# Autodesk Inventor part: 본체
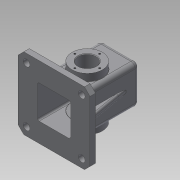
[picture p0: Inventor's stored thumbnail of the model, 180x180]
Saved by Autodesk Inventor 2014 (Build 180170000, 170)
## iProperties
Created: 2016-02
Part Number: 본체
Material: Generic
Document SubType Name: Modeling
Designer: user
Density: 1 g/cm^3
Appearance: Default
Author: user
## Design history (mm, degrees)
sketch "Sketch1"
  geometry: L1 (-35, -60)-(35, -60); L2 (35, -60)-(35, 60); L3 (35, 60)-(-35, 60); L4 (-35, 60)-(-35, -60); L5 (-35, -60)-(35, 60); L6 (35, -60)-(-35, 60); 1 further point
  constraints: 12 end point, 2 midpoint
extrude "Extrusion1" new body sketch "Sketch1" stored distance "d6" = 70; taper "d7" = 0 deg
sketch "Sketch3"
  geometry: L1 (70, -70)-(70, 0) reference; L2 (0, 0)-(70, 0) reference; L3 (0, 0)-(0, -70) reference; L4 (70, -70)-(0, -70) reference; L5 (-30, -100)-(100, -100); L6 (100, -100)-(100, 30); L7 (100, 30)-(-30, 30); L8 (-30, 30)-(-30, -100); L9 (-30, -100)-(100, 30); L10 (100, -100)-(-30, 30); 1 further point
  constraints: 12 end point, 2 midpoint
extrude "Extrusion2" join sketch "Sketch3" distance "d9" = 10; taper "d10" = 0 deg
sketch "Sketch4"
  geometry: C1 r 27.5 at (0, 0); 1 further point
  constraints: 1 centre point, 1 coincident
extrude "Extrusion3" join sketch "Sketch4" distance "d11" = 13; taper "d12" = 0 deg
mirror "Mirror1"
sketch "Sketch5"
  geometry: L1 (-65, -60)-(-65, -50) reference; L2 (-65, -50)-(-35, -50) reference; L3 (-35, -50)-(-35, 60) reference; L4 (-35, 60)-(35, 60) reference; L5 (35, 60)-(35, -50) reference; L6 (35, -50)-(65, -50) reference; L7 (65, -50)-(65, -60) reference; L8 (65, -60)-(-65, -60) reference; L9 (20, 60)-(18.237, 70); L10 (18.237, 70)-(0, 70); L11 (0, 70)-(0, 60); L12 (0, 60)-(20, 60); 1 further point
  constraints: 8 end point, 1 horizontal, 1 midpoint, 1 point on line, 1 vertical
  dimensions: "d13" = 20 distance of L11.end L9.start; "d14" = 100 deg angle of L4 L9; "d15" = 10 distance of L10.end L11.end
revolve "Revolution1" sketch "Sketch5" stored, may be unused: angle "d16" = 90 deg
sketch "Sketch6"
  geometry: L1 (-65, -60)-(-65, -50) reference; L2 (-65, -50)-(-35, -50) reference; L3 (-35, -50)-(-35, 60) reference; L4 (-35, 60)-(-20, 60) reference; L5 (-20, 60)-(-18.237, 70) reference; L6 (-18.237, 70)-(18.237, 70) reference; L7 (18.237, 70)-(20, 60) reference; L8 (20, 60)-(35, 60) reference; L9 (35, 60)-(35, -50) reference; L10 (35, -50)-(65, -50) reference; L11 (65, -50)-(65, -60) reference; L12 (65, -60)-(-65, -60) reference; L13 (-50, -50)-(-35, 35.069); 1 further point
  constraints: 2 end point, 1 midpoint, 1 point on line
  dimensions: "d17" = 100 deg angle of L2 L13; "d18" = 15 distance from line of L1 L13.start
feature "Rib1" sketch "Sketch6" dims "d19" = 1, "d20" = 10, "d21" = 0, "d22" = 0, "d23" = 1, "d24" = 1
mirror "Mirror2"
sketch "Sketch8"
  geometry: L1 (27.5, 48)-(27.5, 35) reference; L2 (27.5, 35)-(60, 35) reference; L3 (60, 35)-(60, 20) reference; L4 (60, 20)-(70, 18.237) reference; L5 (70, 18.237)-(70, -18.237) reference; L6 (70, -18.237)-(60, -20) reference; L7 (60, -20)-(60, -35) reference; L8 (60, -35)-(27.5, -35) reference; L9 (27.5, -35)-(27.5, -48) reference; L10 (27.5, -48)-(-27.5, -48) reference; L11 (-27.5, -48)-(-27.5, -35) reference; L12 (-27.5, -35)-(-50, -35) reference; L13 (-50, -35)-(-50, -65) reference; L14 (-50, -65)-(-60, -65) reference; L15 (-60, -65)-(-60, 65) reference; L16 (-60, 65)-(-50, 65) reference; L17 (-50, 65)-(-50, 35) reference; L18 (-50, 35)-(-27.5, 35) reference; L19 (-27.5, 35)-(-27.5, 48) reference; L20 (-27.5, 48)-(27.5, 48) reference; L21 (-60, 30)-(55, 30); L22 (55, 30)-(55, -30); L23 (55, -30)-(-60, -30); L24 (-60, 30)-(-60, -30); 1 further point
  constraints: 8 end point, 2 point on line
  dimensions: "d25" = 5 distance between parallel lines of L18 L21; "d26" = 5 distance between parallel lines of L23 L12; "d27" = 5 distance between parallel lines of L7 L22
extrude "Extrusion4" cut sketch "Sketch8" stored distance "d28" = 60; taper "d29" = 0 deg
sketch "Sketch9"
  geometry: L1 (27.5, 48)-(27.5, 35) reference; L2 (27.5, 35)-(60, 35) reference; L3 (60, 35)-(60, 20) reference; L4 (60, 20)-(70, 18.237) reference; L5 (70, 18.237)-(70, -18.237) reference; L6 (70, -18.237)-(60, -20) reference; L7 (60, -20)-(60, -35) reference; L8 (60, -35)-(27.5, -35) reference; L9 (27.5, -35)-(27.5, -48) reference; L10 (27.5, -48)-(-27.5, -48) reference; L11 (-27.5, -48)-(-27.5, -35) reference; L12 (-27.5, -35)-(-50, -35) reference; L13 (-50, -35)-(-50, -65) reference; L14 (-50, -65)-(-60, -65) reference; L15 (-60, -65)-(-60, -30) reference; L16 (-60, -30)-(55, -30) reference; L17 (55, -30)-(55, 30) reference; L18 (55, 30)-(-60, 30) reference; L19 (-60, 30)-(-60, 65) reference; L20 (-60, 65)-(-50, 65) reference; L21 (-50, 65)-(-50, 35) reference; L22 (-50, 35)-(-27.5, 35) reference; L23 (-27.5, 35)-(-27.5, 48) reference; L24 (-27.5, 48)-(27.5, 48) reference; L25 (27.5, 30)-(0, 30); L26 (0, 30)-(0, 23); L27 (27.5, 30)-(20.5, 23); L28 (0, 23)-(20.5, 23); 1 further point
  constraints: 8 end point, 2 point on line
revolve "Revolution2" sketch "Sketch9" stored, may be unused: angle "d33" = 90 deg
mirror "Mirror3"
fillet "Fillet1" dims "d34" = 8
fillet "Fillet2" dims "d35" = 3
chamfer "Chamfer1" distance "d36" = 10; stored, may be unused: second distance "d37" = 2, angle "d38" = 45 deg
sketch "Sketch10"
  geometry: L1 (90, 100)-(-20, 100) reference; L2 (-30, 90)-(-30, -20) reference; C1 r 6 at (-15, 85); 1 further point
  constraints: 1 centre point
  dimensions: "d39" = 12 diameter of C1; "d40" = 15 distance from line of C1.centre L1; "d41" = 15 distance from line of C1.centre L2
extrude "Extrusion5" cut sketch "Sketch10" stored distance "d42" = 60; taper "d43" = 0 deg
mirror "Mirror4"
pattern_linear "Rectangular Pattern1"
fillet "Fillet3" dims "d47" = 8
fillet "Fillet4" dims "d48" = 0.5
sketch "Sketch11"
  geometry: L1 (-20.762, 45.72)-(20.762, 45.72); L2 (20.762, 45.72)-(20.762, 34.28); L3 (20.762, 34.28)-(-20.762, 34.28); L4 (-20.762, 34.28)-(-20.762, 45.72); L5 (-20.762, 45.72)-(20.762, 34.28); L6 (20.762, 45.72)-(-20.762, 34.28); L7 (-18.237, 70)-(18.237, 70) reference; L8 (35, -50)-(35, 52) reference; 1 further point
  constraints: 4 end point, 1 midpoint, 2 other
  dimensions: "d49" = 30 distance from line of point (0, 40) L7; "d50" = 35 distance from line of L8 point (0, 40)
emboss "Emboss1" sketch "Sketch11" dims "d51" = 0.5, "d52" = 0
fillet "Fillet5" dims "d53" = 3
fillet "Fillet6" dims "d54" = 3
fillet "Fillet7" dims "d55" = 3
hole "Hole1" diameter "d58" = 28; stored, may be unused: countersink angle "d62" = 90 deg, drill point angle "d64" = 0 deg; dims "d56" = 10, "d57" = 10, "d59" = 6, "d60" = 4, "d61" = 2, "d63" = 4
hole "Hole2" diameter "d67" = 21; stored, may be unused: countersink angle "d71" = 90 deg, drill point angle "d73" = 0 deg; dims "d65" = 10, "d66" = 10, "d68" = 6, "d69" = 4, "d70" = 2, "d72" = 4
hole "Hole3" diameter "d76" = 32; stored, may be unused: countersink angle "d80" = 90 deg, drill point angle "d82" = 0 deg; dims "d74" = 10, "d75" = 10, "d77" = 6, "d78" = 4, "d79" = 2, "d81" = 4
sketch "Sketch12"
  geometry: C1 r 27.5 at (0, 0) reference; 2 further points
  constraints: 1 coincident, 1 vertical alignment, 2 other
hole "Hole4" sketch "Sketch12" at (0, 22.5) diameter "d83" = 3.242; stored, may be unused: countersink angle "d87" = 90 deg, drill point angle "d89" = 118 deg; dims "d84" = 8, "d85" = 4, "d86" = 2, "d88" = 10
pattern_circular "Circular Pattern1" dims angle "d91" = 360 deg
mirror "Mirror5"
fillet "Fillet8" dims "d93" = 0.5
chamfer "Chamfer2" distance "d94" = 1; stored, may be unused: second distance "d95" = 2, angle "d96" = 45 deg
fillet "Fillet9" dims "d97" = 3
body "Solid1"
node "Project Cut Edges1"
node "Project Cut Edges2"
node "Project Cut Edges4"
node "Project Cut Edges5"
